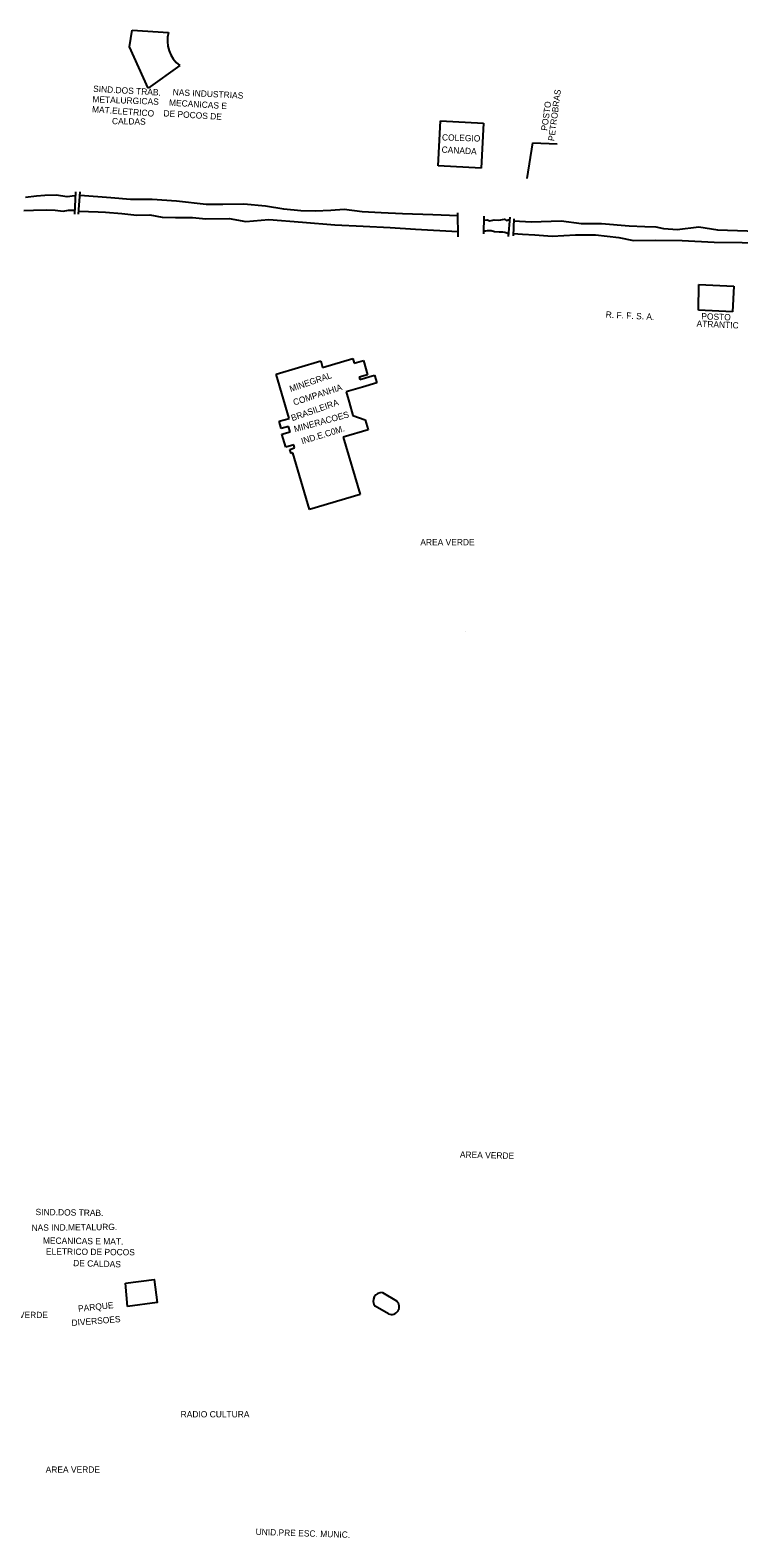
# Model space of a CAD drawing. Extents: x 325899 to 363134, y 7578590 to 7592502.
# Drawn here: x 337060 to 337510, y 7589250 to 7590208 of the extents above; entities that cross this region are included whole.
import ezdxf

# ---------------------------------------------------------------- set-up
doc = ezdxf.new("R2010")
doc.units = 0
for name, color, linetype in [('EDIFEXISTENT', 7, 'Continuous'), ('EDIFIDENTIF', 7, 'Continuous'), ('EDIFOBRAEXIS', 7, 'Continuous')]:
    doc.layers.add(name, color=color, linetype=linetype)

msp = doc.modelspace()

# ---------------------------------------------------------------- linework, layer by layer
at = {"layer": 'EDIFEXISTENT'}
for p, q in [((337122.82, 7590196.97), (337124.46, 7590207.66)), ((337124.46, 7590207.66), (337147.55, 7590206.25)), ((337134.67, 7590170.89), (337122.82, 7590196.97)), ((337154.75, 7590185.21), (337134.67, 7590170.89)), ((337318.76, 7590121.39), (337320.41, 7590150.1)), ((337320.41, 7590150.1), (337347.58, 7590148.56)), ((337347.58, 7590148.56), (337346.06, 7590119.99)), ((337375.28, 7590113.46), (337379.04, 7590136.1)), ((337379.04, 7590136.1), (337394.52, 7590135.33)), ((337346.06, 7590119.99), (337318.76, 7590121.39)), ((337088.48, 7590104.95), (337087.8, 7590090.72)), ((337090.51, 7590090.72), (337091.53, 7590104.95)), ((337331.11, 7590091.59), (337331.24, 7590076.38)), ((337347.94, 7590089.43), (337347.54, 7590078.26)), ((337364.38, 7590088.89), (337363.3, 7590076.51)), ((337366.94, 7590087.68), (337366.53, 7590077.05)), ((337484.3, 7590029.71), (337484.49, 7590046.1)), ((337484.49, 7590046.1), (337506.65, 7590044.97)), ((337506.65, 7590044.97), (337505.81, 7590028.61)), ((337505.81, 7590028.61), (337484.3, 7590029.71)), ((337215.96, 7589989.09), (337244.25, 7589997.48)), ((337244.25, 7589997.48), (337245.46, 7589993.41)), ((337245.46, 7589993.41), (337264.69, 7589999.12)), ((337264.69, 7589999.12), (337265.6, 7589996.04)), ((337265.6, 7589996.04), (337271.32, 7589997.74)), ((337271.32, 7589997.74), (337274, 7589988.72)), ((337224.16, 7589961), (337215.96, 7589989.09)), ((337274, 7589988.72), (337268.67, 7589987.14)), ((337268.67, 7589987.14), (337269.12, 7589985.6)), ((337269.12, 7589985.6), (337278.44, 7589988.36)), ((337279.87, 7589983.55), (337270.77, 7589980.85)), ((337278.44, 7589988.36), (337279.87, 7589983.55)), ((337270.77, 7589980.85), (337260.33, 7589977.76)), ((337260.33, 7589977.76), (337262.24, 7589971.32)), ((337262.24, 7589971.32), (337264.75, 7589962.85)), ((337264.75, 7589962.85), (337272.4, 7589960.05)), ((337217.81, 7589959.12), (337224.16, 7589961)), ((337219.19, 7589954.49), (337217.81, 7589959.12)), ((337223.79, 7589955.86), (337219.19, 7589954.49)), ((337224.8, 7589952.46), (337223.79, 7589955.86)), ((337274.3, 7589953.66), (337258.48, 7589948.97)), ((337272.4, 7589960.05), (337274.3, 7589953.66)), ((337219.63, 7589950.93), (337224.8, 7589952.46)), ((337222.06, 7589942.71), (337219.63, 7589950.93)), ((337227.08, 7589944.2), (337222.06, 7589942.71)), ((337227.68, 7589942.19), (337227.08, 7589944.2)), ((337258.48, 7589948.97), (337269.24, 7589912.7)), ((337224.65, 7589941.29), (337227.68, 7589942.19)), ((337225.41, 7589938.73), (337224.65, 7589941.29)), ((337226.55, 7589939.07), (337225.41, 7589938.73)), ((337237.19, 7589903.19), (337226.55, 7589939.07)), ((337269.24, 7589912.7), (337237.19, 7589903.19))]:
    msp.add_line(p, q, dxfattribs=at)
msp.add_arc((337166.57, 7590201.01), 19.74, 164.58658, 233.19128, dxfattribs=at)
at = {"layer": 'EDIFOBRAEXIS'}
for points in [[(337088.14, 7590102.37), (337083.24, 7590101.83), (337076.17, 7590102.84), (337069.03, 7590102.55), (337063.63, 7590102.11), (337056.76, 7590101.41)], [(337331.3, 7590089.74), (337315.37, 7590090.32), (337296.22, 7590090.85), (337282.74, 7590091.5), (337270.5, 7590092.26), (337259.2, 7590093.65), (337250.68, 7590093.13), (337240.76, 7590092.68), (337231.69, 7590092.83), (337220.86, 7590093.88), (337209.13, 7590095.78), (337195.41, 7590097.15), (337182.02, 7590096.84), (337171.4, 7590096.96), (337152.66, 7590099.03), (337137.28, 7590099.99), (337123.38, 7590100.15), (337110.92, 7590101.02), (337091.37, 7590102.56)], [(337055.79, 7590093.02), (337061.91, 7590093.32), (337070.07, 7590093.59), (337075.61, 7590093.25), (337080.7, 7590092.63), (337083.99, 7590093.36)], [(337083.99, 7590093.36), (337087.61, 7590093.23)], [(337090.66, 7590092.59), (337102.93, 7590092.28), (337107.6, 7590092.1), (337117.97, 7590091.09), (337127.51, 7590090.04), (337135.64, 7590090.32), (337143.52, 7590088.89), (337151.95, 7590088.7), (337162.9, 7590088.72), (337171.19, 7590087.74), (337186.03, 7590087.9), (337196.78, 7590086.17), (337211.25, 7590087.31), (337232.69, 7590085.6), (337253.27, 7590083.96), (337271.17, 7590083.08), (337288.4, 7590082.31), (337304.54, 7590081.13), (337331.24, 7590079.74)], [(337348.08, 7590086.88), (337350.07, 7590087.21), (337351.63, 7590086.6), (337354.46, 7590087.11), (337357.28, 7590086.96), (337361.03, 7590087.63), (337362.15, 7590086.7), (337363.97, 7590087.28)], [(337347.94, 7590080.06), (337349.21, 7590080.06), (337350.23, 7590080.32), (337352.6, 7590080.28), (337354.57, 7590079.64), (337357.69, 7590079.56), (337359.97, 7590079.42), (337361.27, 7590079.25), (337361.8, 7590079.01), (337363.44, 7590078.4)], [(337366.49, 7590078.47), (337372.5, 7590078.02), (337380.3, 7590077.71), (337391.33, 7590076.69), (337406.08, 7590077.64), (337418.84, 7590077.63), (337433.64, 7590075.83), (337442.91, 7590073.98), (337457.01, 7590074.12), (337473.88, 7590074.07), (337494.06, 7590072.97), (337511.89, 7590072.65), (337532.26, 7590072.16), (337547.62, 7590069.95), (337562.82, 7590069.21), (337571.86, 7590068.45), (337575.79, 7590068.11), (337584.45, 7590068.24), (337588.75, 7590068.4), (337592.62, 7590068.77), (337599, 7590067.91)], [(337599.37, 7590075.34), (337594.35, 7590075.22), (337587.28, 7590076.12), (337580.67, 7590076.03), (337574.59, 7590076.74), (337566.31, 7590078.45), (337556.97, 7590077.44), (337546.95, 7590078.52), (337532.14, 7590078.66), (337523.25, 7590078.69), (337515.11, 7590079.99), (337496.4, 7590080.5), (337484.41, 7590082.56), (337470.59, 7590080.88), (337462.17, 7590081.45), (337457.41, 7590082.4), (337450.17, 7590082.7), (337440.06, 7590083.12), (337422.69, 7590084.6), (337409.86, 7590084.59), (337397.05, 7590086.3), (337377.91, 7590085.63), (337366.93, 7590086.35)], [(337336.46, 7589825.69), (337336.44, 7589825.72)], [(337120.22, 7589411.58), (337138.37, 7589413.8), (337140.39, 7589399.28), (337121.63, 7589396.76)], [(337121.63, 7589396.76), (337120.22, 7589411.58)], [(337283.54, 7589405.5), (337292.48, 7589400.18)], [(337287.29, 7589392), (337278.78, 7589396.89)]]:
    msp.add_lwpolyline(points, dxfattribs=at)
for centre, radius, start, end in [((337282.9, 7589400.24), 5.31, 83.02404, 219.11617), ((337289.21, 7589396.52), 4.91, 247.05944, 48.15887)]:
    msp.add_arc(centre, radius, start, end, dxfattribs=at)

# ---------------------------------------------------------------- texts
at = {"layer": 'EDIFIDENTIF'}
for s, rotation, p in [('METALURGICAS', 357.71, (337099.16, 7590161.86)), ('SIND.DOS TRAB.', 356.68226, (337099.6, 7590168.51)), ('MECANICAS E', 356.45834, (337147.79, 7590159.72)), ('NAS INDUSTRIAS', 357.07898, (337150.16, 7590166.36)), ('PETROBRAS', 82.59197, (337392.6, 7590136.98)), ('MAT.ELETRICO', 355.90782, (337098.88, 7590155.49)), ('DE POCOS DE', 356.43889, (337144.28, 7590152.88)), ('POSTO', 82.10904, (337388.11, 7590143.57)), ('CALDAS', 358.86723, (337111.65, 7590147.94)), ('COLEGIO', 358.24776, (337321.22, 7590137.59)), ('CANADA', 356.78091, (337320.95, 7590129.86)), ('R. F. F. S. A.', 357.16493, (337425.2, 7590025.01)), ('ATRANTIC', 357.45645, (337482.9, 7590019.25)), ('POSTO', 357.86808, (337485.93, 7590023.91)), ('MINEGRAL', 18.84023, (337225.21, 7589977.69)), ('COMPANHIA', 17.99771, (337227.44, 7589969.12)), ('BRASILEIRA', 19.18853, (337226.23, 7589959.17)), ('MINERACOES', 15.54112, (337227.89, 7589952.14)), ('IND.E.C0M.', 17.00109, (337232.52, 7589944.51)), ('AREA VERDE', 359.96592, (337307.53, 7589880.32)), ('AREA VERDE', 358.5554, (337332.61, 7589491.28)), ('SIND.DOS TRAB.', 359.16693, (337063.12, 7589454.77)), ('NAS IND.METALURG.', 0.61612, (337060.59, 7589444.72)), ('MECANICAS E MAT.', 359.31146, (337067.76, 7589436.62)), ('ELETRICO DE POCOS', 359.44545, (337069.73, 7589429.69)), ('DE CALDAS', 358.45327, (337086.97, 7589422.33)), ('PARQUE', 6.08793, (337090.35, 7589393.27)), ('AREA VERDE', 359.97973, (337036.51, 7589389.33)), ('DIVERSOES', 4.6909, (337086.12, 7589384.26)), ('AREA VERDE', 0.14375, (337069.57, 7589291.01)), ('UNID.PRE ESC. MUNIC.', 358.19436, (337202.87, 7589251.56))]:
    msp.add_text(s, height=4, rotation=rotation, dxfattribs=at).set_placement(p)
msp.add_text('RADIO CULTURA', height=4, dxfattribs=at).set_placement((337155.3, 7589326.22))

doc.saveas('drawing.dxf')
